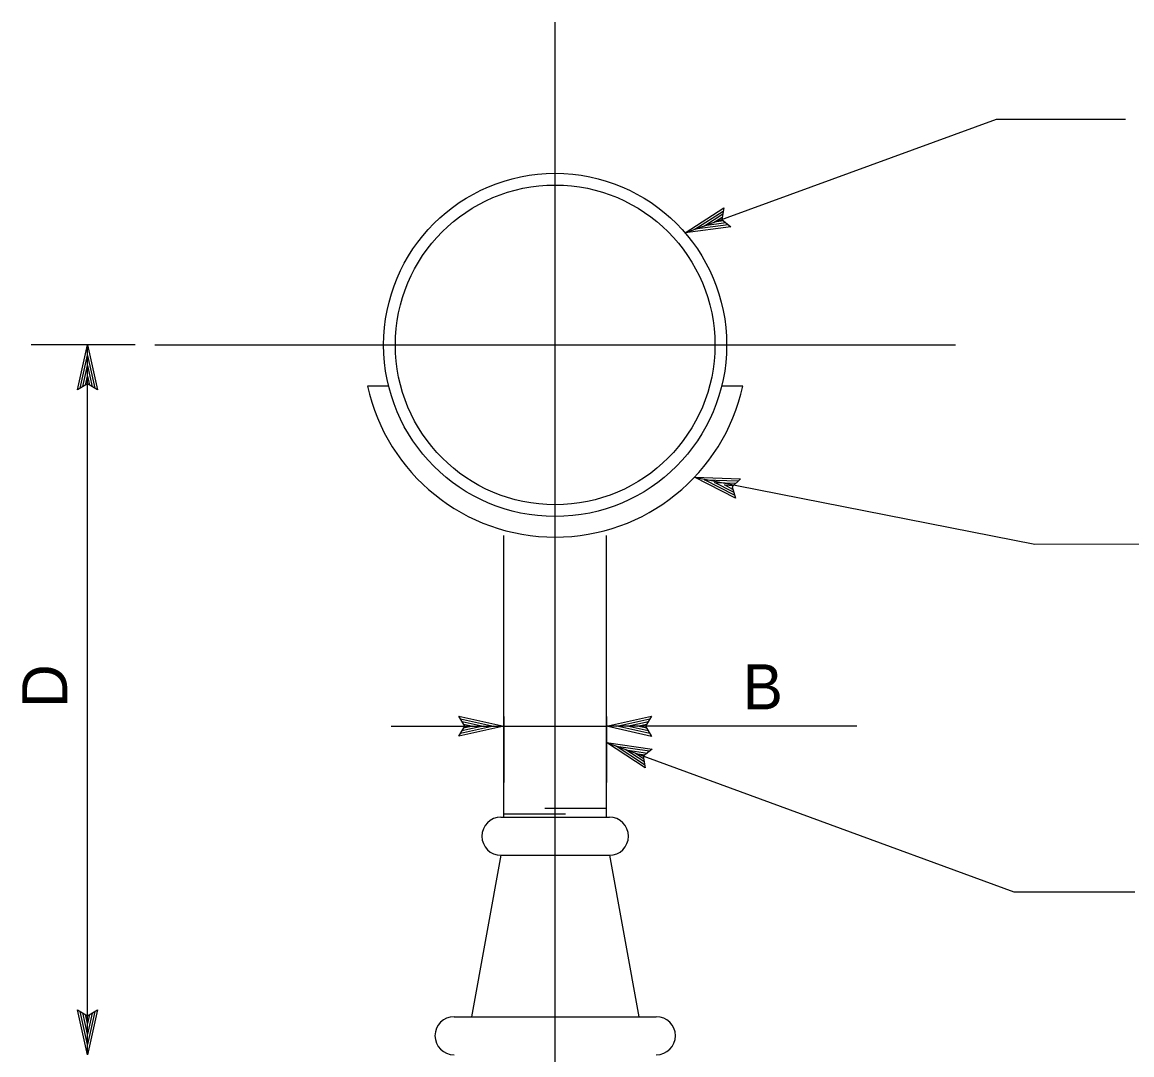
# Model space of a CAD drawing. Extents: x -123486 to -116575, y -107066 to -101122.
# Drawn here: x -117302.7 to -117154.8, y -101832.8 to -101695.3 of the extents above; entities that cross this region are included whole.
import ezdxf

# ---------------------------------------------------------------- set-up
doc = ezdxf.new("R2010")
doc.units = 0
for name, color, linetype in [('G-MARK', 7, 'Continuous'), ('G-TEXT', 7, 'Continuous'), ('Misc CnstDet(22)', 7, 'Continuous')]:
    doc.layers.add(name, color=color, linetype=linetype)

msp = doc.modelspace()

# ---------------------------------------------------------------- linework, layer by layer
at = {"layer": 'G-MARK'}
for p, q in [((-117287.59, -101738.23), (-117301.45, -101738.23)), ((-117293.95, -101832.76), (-117293.95, -101738.23)), ((-117253.48, -101789.01), (-117238.48, -101789.01)), ((-117191.45, -101789.01), (-117224.81, -101789.01))]:
    msp.add_line(p, q, dxfattribs=at)
for points in [[(-117214.35, -101723.29), (-117172.86, -101708.15), (-117155.67, -101708.15)], [(-117213.09, -101755.84), (-117167.73, -101764.75), (-117153.45, -101764.72)], [(-117224.81, -101791.19), (-117170.56, -101811.07), (-117154.43, -101811.07)]]:
    msp.add_lwpolyline(points, dxfattribs=at)
at = {"layer": 'G-TEXT'}
for p, q in [((-117214.35, -101723.29), (-117209.17, -101719.99)), ((-117213.04, -101722.81), (-117209.26, -101720.41)), ((-117211.75, -101722.35), (-117209.31, -101720.79)), ((-117209.17, -101719.99), (-117209.46, -101721.51)), ((-117209.17, -101719.99), (-117209.17, -101719.99)), ((-117208.58, -101722.24), (-117213.05, -101722.82)), ((-117208.92, -101721.98), (-117211.75, -101722.35)), ((-117210.45, -101721.88), (-117209.41, -101721.21)), ((-117209.21, -101721.71), (-117210.45, -101721.88)), ((-117209.46, -101721.51), (-117208.25, -101722.5)), ((-117208.25, -101722.5), (-117214.35, -101723.29)), ((-117214.35, -101723.29), (-117214.35, -101723.29)), ((-117208.25, -101722.5), (-117208.25, -101722.5)), ((-117295.29, -101744.23), (-117293.95, -101738.23)), ((-117293.95, -101738.23), (-117293.95, -101738.23)), ((-117293.95, -101738.23), (-117292.62, -101744.23)), ((-117294.94, -101744.01), (-117293.95, -101739.61)), ((-117293.95, -101739.62), (-117292.98, -101743.99)), ((-117294.58, -101743.77), (-117293.95, -101740.99)), ((-117293.95, -101740.99), (-117293.33, -101743.81)), ((-117294.23, -101743.6), (-117293.96, -101742.37)), ((-117293.96, -101742.37), (-117293.69, -101743.58)), ((-117293.95, -101743.43), (-117295.29, -101744.23)), ((-117295.29, -101744.23), (-117295.29, -101744.23)), ((-117292.62, -101744.23), (-117293.95, -101743.43)), ((-117292.62, -101744.23), (-117292.62, -101744.23)), ((-117207.62, -101758.64), (-117213.09, -101755.84)), ((-117213.09, -101755.84), (-117213.09, -101755.84)), ((-117213.09, -101755.84), (-117206.95, -101756.06)), ((-117207.74, -101758.24), (-117211.76, -101756.19)), ((-117211.75, -101756.19), (-117207.27, -101756.34)), ((-117206.95, -101756.06), (-117208.06, -101757.14)), ((-117206.95, -101756.06), (-117206.95, -101756.06)), ((-117207.88, -101757.84), (-117210.42, -101756.54)), ((-117210.42, -101756.54), (-117207.53, -101756.64)), ((-117207.96, -101757.46), (-117209.08, -101756.88)), ((-117209.08, -101756.88), (-117207.84, -101756.93)), ((-117208.06, -101757.14), (-117207.62, -101758.64)), ((-117207.62, -101758.64), (-117207.62, -101758.64)), ((-117243.68, -101789.01), (-117244.48, -101787.67)), ((-117244.48, -101787.67), (-117244.48, -101787.67)), ((-117244.48, -101787.67), (-117238.48, -101789.01)), ((-117244.27, -101788.02), (-117239.86, -101789.01)), ((-117244.03, -101788.38), (-117241.25, -101789)), ((-117243.86, -101788.73), (-117242.63, -101789)), ((-117224.81, -101789.01), (-117218.81, -101787.68)), ((-117223.42, -101789), (-117219.05, -101788.04)), ((-117222.05, -101789.01), (-117219.22, -101788.38)), ((-117220.67, -101789.01), (-117219.46, -101788.74)), ((-117218.81, -101787.68), (-117219.61, -101789.01)), ((-117218.81, -101787.68), (-117218.81, -101787.68)), ((-117238.48, -101789.01), (-117244.48, -101790.34)), ((-117244.48, -101790.34), (-117243.68, -101789.01)), ((-117244.48, -101790.34), (-117244.48, -101790.34)), ((-117239.87, -101789.01), (-117244.25, -101789.98)), ((-117241.25, -101789), (-117244.07, -101789.63)), ((-117242.63, -101789), (-117243.84, -101789.27)), ((-117238.48, -101789.01), (-117238.48, -101789.01)), ((-117218.81, -101790.35), (-117224.81, -101789.01)), ((-117224.81, -101789.01), (-117224.81, -101789.01)), ((-117219.03, -101789.99), (-117223.43, -101789.01)), ((-117219.26, -101789.63), (-117222.05, -101789.01)), ((-117219.44, -101789.28), (-117220.67, -101789.01)), ((-117219.61, -101789.01), (-117218.81, -101790.35)), ((-117218.81, -101790.35), (-117218.81, -101790.35)), ((-117219.66, -101794.55), (-117224.81, -101791.19)), ((-117224.81, -101791.19), (-117224.81, -101791.19)), ((-117224.81, -101791.19), (-117218.73, -101792.05)), ((-117219.74, -101794.14), (-117223.52, -101791.68)), ((-117223.51, -101791.68), (-117219.07, -101792.3)), ((-117219.83, -101793.72), (-117222.22, -101792.16)), ((-117222.22, -101792.16), (-117219.36, -101792.57)), ((-117219.88, -101793.34), (-117220.93, -101792.65)), ((-117220.93, -101792.65), (-117219.7, -101792.82)), ((-117218.73, -101792.05), (-117219.94, -101793.01)), ((-117219.94, -101793.01), (-117219.66, -101794.55)), ((-117218.73, -101792.05), (-117218.73, -101792.05)), ((-117219.66, -101794.55), (-117219.66, -101794.55)), ((-117293.95, -101832.76), (-117295.28, -101826.76)), ((-117295.28, -101826.76), (-117295.28, -101826.76)), ((-117295.28, -101826.76), (-117293.95, -101827.56)), ((-117293.96, -101831.37), (-117294.92, -101826.99)), ((-117293.95, -101829.99), (-117294.58, -101827.17)), ((-117293.95, -101827.56), (-117292.61, -101826.76)), ((-117292.61, -101826.76), (-117293.95, -101832.76)), ((-117292.97, -101826.97), (-117293.95, -101831.38)), ((-117293.33, -101827.21), (-117293.95, -101829.99)), ((-117292.61, -101826.76), (-117292.61, -101826.76)), ((-117293.95, -101828.61), (-117294.22, -101827.4)), ((-117293.67, -101827.38), (-117293.95, -101828.61)), ((-117293.95, -101832.76), (-117293.95, -101832.76))]:
    msp.add_line(p, q, dxfattribs=at)
at = {"layer": 'Misc CnstDet(22)'}
for p, q in [((-117231.65, -101955.02), (-117231.65, -101695.26)), ((-117284.97, -101738.23), (-117178.33, -101738.23)), ((-117256.64, -101743.69), (-117253.84, -101743.69)), ((-117209.46, -101743.69), (-117206.65, -101743.69)), ((-117238.48, -101801.12), (-117238.48, -101763.62)), ((-117224.81, -101801.12), (-117224.81, -101763.62)), ((-117238.48, -101787.73), (-117238.48, -101796.51)), ((-117224.81, -101787.73), (-117224.81, -101796.51)), ((-117238.48, -101789.01), (-117224.81, -101789.01)), ((-117230.28, -101800.73), (-117238.48, -101800.73)), ((-117224.81, -101799.94), (-117233.01, -101799.94)), ((-117238.87, -101801.12), (-117224.42, -101801.12)), ((-117238.87, -101806.19), (-117242.78, -101827.68)), ((-117238.87, -101806.19), (-117224.42, -101806.19)), ((-117224.42, -101806.19), (-117220.51, -101827.68)), ((-117245.12, -101827.68), (-117218.17, -101827.68))]:
    msp.add_line(p, q, dxfattribs=at)
for radius in [22.85, 21.29]:
    msp.add_circle((-117231.65, -101738.23), radius, dxfattribs=at)
for centre, radius, start, end in [((-117231.65, -101738.23), 25.59, 192.3416, 347.6584), ((-117238.87, -101803.65), 2.54, 90, 270), ((-117224.42, -101803.65), 2.54, 270, 90), ((-117245.12, -101830.22), 2.54, 90, 270), ((-117218.17, -101830.22), 2.54, 270, 90)]:
    msp.add_arc(centre, radius, start, end, dxfattribs=at)

# ---------------------------------------------------------------- texts
msp.add_text('D', height=6, rotation=90, dxfattribs=at).set_placement((-117296.65, -101786.55))
msp.add_text('B', height=6, dxfattribs=at).set_placement((-117206.66, -101786.76))

doc.saveas('drawing.dxf')
